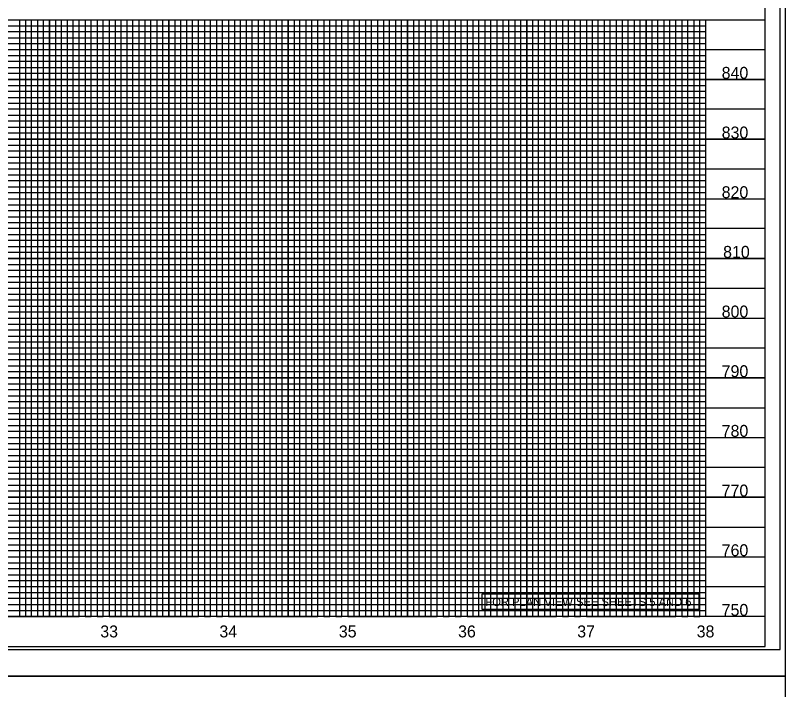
# Model space of a CAD drawing. Extents: x 1755181 to 1757273, y 729911 to 735411.
# Drawn here: x 1756219 to 1756865, y 734300 to 734864 of the extents above; entities that cross this region are included whole.
import ezdxf

# ---------------------------------------------------------------- set-up
doc = ezdxf.new("R2010")
doc.units = 0
for name, color, linetype in [('Exist Vertical Profile Horizontal Axis Label Major', 7, 'Continuous'), ('Exist Vertical Profile Vertical Axis Label', 7, 'Continuous'), ('Prop Grid Mask', 7, 'Continuous'), ('Prop VPI Label', 7, 'Continuous'), ('Scratch_Level_3', 7, 'Continuous'), ('Sheet Cutting Line CELL', 7, 'Continuous'), ('Sheet DOT Grid CELL', 7, 'Continuous'), ('Sheet Plot Border Inside CELL', 7, 'Continuous'), ('Sheet Plot Border Outside CELL', 7, 'Continuous'), ('Sheet Profile CELL', 7, 'Continuous'), ('Sheet Profile Grid Major CELL', 7, 'Continuous'), ('Sheet Profile Grid Middle CELL', 7, 'Continuous'), ('Sheet Profile Grid Minor CELL', 7, 'Continuous')]:
    doc.layers.add(name, color=color, linetype=linetype)

msp = doc.modelspace()

# ---------------------------------------------------------------- linework, layer by layer
at = {"layer": 'Prop Grid Mask'}
msp.add_lwpolyline([(1756610.25, 734379.75), (1756792.01, 734379.75), (1756792.01, 734366.55), (1756610.25, 734366.55)], close=True, dxfattribs=at)
at = {"layer": 'Scratch_Level_3'}
msp.add_lwpolyline([(1755397.67, 734860.78), (1756797.67, 734860.78), (1756797.67, 734360.78), (1755397.67, 734360.78)], close=True, dxfattribs=at)
at = {"layer": 'Sheet Cutting Line CELL'}
msp.add_line((1755180.67, 734310.78), (1756864.67, 734310.78), dxfattribs=at)
at = {"layer": 'Sheet DOT Grid CELL'}
for p, q in [((1755347.67, 734860.78), (1756847.56, 734860.78)), ((1756247.67, 734860.78), (1756247.67, 734360.78)), ((1756297.67, 734860.78), (1756297.67, 734360.78)), ((1756347.67, 734860.78), (1756347.67, 734360.78)), ((1756397.67, 734860.78), (1756397.67, 734360.78)), ((1756447.67, 734860.78), (1756447.67, 734360.78)), ((1756497.67, 734860.78), (1756497.67, 734360.78)), ((1756547.67, 734860.78), (1756547.67, 734360.78)), ((1756597.67, 734860.78), (1756597.67, 734360.78)), ((1756647.67, 734860.78), (1756647.67, 734360.78)), ((1756697.67, 734860.78), (1756697.67, 734360.78)), ((1756747.67, 734860.78), (1756747.67, 734360.78)), ((1756797.67, 734860.78), (1756797.67, 734360.78)), ((1755347.67, 734810.78), (1756847.56, 734810.78)), ((1755347.67, 734760.78), (1756847.56, 734760.78)), ((1755347.67, 734710.78), (1756847.56, 734710.78)), ((1755347.67, 734660.78), (1756847.56, 734660.78)), ((1755347.67, 734610.78), (1756847.56, 734610.78)), ((1755347.67, 734560.78), (1756847.56, 734560.78)), ((1755347.67, 734510.78), (1756847.56, 734510.78)), ((1755347.67, 734460.78), (1756847.56, 734460.78)), ((1755347.67, 734410.78), (1756847.56, 734410.78))]:
    msp.add_line(p, q, dxfattribs=at)
at = {"layer": 'Sheet Plot Border Inside CELL'}
msp.add_lwpolyline([(1755193.67, 734333.23), (1756860.17, 734333.23), (1756860.17, 735388.33), (1755193.67, 735388.33)], close=True, dxfattribs=at)
at = {"layer": 'Sheet Plot Border Outside CELL'}
for points in [[(1755180.67, 734310.78), (1756864.67, 734310.78), (1756864.67, 735410.78), (1755180.67, 735410.78)], [(1755180.67, 733210.78), (1756864.67, 733210.78), (1756864.67, 734310.78), (1755180.67, 734310.78)]]:
    msp.add_lwpolyline(points, close=True, dxfattribs=at)
at = {"layer": 'Sheet Profile CELL'}
for p, q in [((1755347.67, 734860.78), (1756847.67, 734860.78)), ((1756847.67, 734360.78), (1755347.67, 734360.78)), ((1755347.67, 734335.78), (1756847.67, 734335.78))]:
    msp.add_line(p, q, dxfattribs=at)
msp.add_lwpolyline([(1756847.67, 735385.78), (1755347.67, 735385.78), (1755347.67, 734335.78), (1756847.67, 734335.78)], close=True, dxfattribs=at)
at = {"layer": 'Sheet Profile Grid Major CELL'}
for p, q in [((1756247.67, 734860.78), (1756297.67, 734860.78)), ((1756347.67, 734860.78), (1756397.67, 734860.78)), ((1756447.67, 734860.78), (1756497.67, 734860.78)), ((1756547.67, 734860.78), (1756597.67, 734860.78)), ((1756647.67, 734860.78), (1756697.67, 734860.78)), ((1756747.67, 734860.78), (1756797.67, 734860.78)), ((1756747.67, 734360.78), (1756747.67, 734360.78)), ((1756797.67, 734361.07), (1756797.67, 734361.07))]:
    msp.add_line(p, q, dxfattribs=at)
for points in [[(1756197.67, 734360.78), (1756247.67, 734360.78), (1756247.67, 734860.78), (1756297.67, 734860.78), (1756297.67, 734360.78), (1756347.67, 734360.78), (1756347.67, 734860.78), (1756397.67, 734860.78), (1756397.67, 734360.78), (1756447.67, 734360.78), (1756447.67, 734860.78), (1756497.67, 734860.78), (1756497.67, 734360.78), (1756547.67, 734360.78), (1756547.67, 734860.78), (1756597.67, 734860.78), (1756597.67, 734360.78), (1756647.67, 734360.78), (1756647.67, 734860.78), (1756697.67, 734860.78), (1756697.67, 734360.78), (1756747.67, 734360.78), (1756747.67, 734360.78), (1756747.67, 734860.78), (1756797.67, 734860.78), (1756797.67, 734360.78)], [(1756847.67, 734810.78), (1755347.67, 734810.78)], [(1756847.67, 734760.78), (1755347.67, 734760.78), (1755347.67, 734710.78), (1756847.67, 734710.78)], [(1756847.67, 734660.78), (1755347.67, 734660.78), (1755347.67, 734610.78), (1756847.67, 734610.78)], [(1756847.67, 734560.78), (1755347.67, 734560.78), (1755347.67, 734510.78), (1756847.67, 734510.78)], [(1756847.67, 734460.78), (1755347.67, 734460.78), (1755347.67, 734460.78), (1755347.67, 734410.78), (1756847.67, 734410.78)], [(1756847.67, 734360.78), (1755347.67, 734360.78)]]:
    msp.add_lwpolyline(points, dxfattribs=at)
at = {"layer": 'Sheet Profile Grid Middle CELL'}
for points in [[(1756172.67, 734860.78), (1756222.67, 734860.78), (1756222.67, 734360.78), (1756272.67, 734360.78), (1756272.67, 734860.78), (1756322.67, 734860.78), (1756322.67, 734360.78), (1756372.67, 734360.78), (1756372.67, 734860.78), (1756422.67, 734860.78), (1756422.67, 734360.78), (1756472.67, 734360.78), (1756472.67, 734860.78), (1756522.67, 734860.78), (1756522.67, 734360.78), (1756572.67, 734360.78), (1756572.67, 734860.78), (1756622.67, 734860.78), (1756622.67, 734360.78), (1756672.67, 734360.78), (1756672.67, 734860.78), (1756722.67, 734860.78), (1756722.67, 734360.78), (1756772.67, 734360.78), (1756772.67, 734860.78)], [(1755347.67, 734835.78), (1756847.67, 734835.78)], [(1756847.67, 734785.78), (1755347.67, 734785.78), (1755347.67, 734735.78), (1756847.67, 734735.78)], [(1756847.67, 734685.78), (1755347.67, 734685.78), (1755347.67, 734635.78), (1756847.67, 734635.78)], [(1756847.67, 734585.78), (1755347.67, 734585.78), (1755347.67, 734535.78), (1756847.67, 734535.78)], [(1756847.67, 734485.78), (1755347.67, 734485.78), (1755347.67, 734435.78), (1756847.67, 734435.78)], [(1756847.67, 734385.78), (1755347.67, 734385.78)]]:
    msp.add_lwpolyline(points, dxfattribs=at)
at = {"layer": 'Sheet Profile Grid Minor CELL'}
for p, q in [((1755397.67, 734855.78), (1756797.67, 734855.78)), ((1756797.67, 734850.78), (1755397.67, 734850.78)), ((1755397.67, 734845.78), (1756797.67, 734845.78)), ((1756797.67, 734840.78), (1755397.67, 734840.78)), ((1755397.67, 734830.78), (1756797.67, 734830.78)), ((1756797.67, 734825.78), (1755397.67, 734825.78)), ((1755397.67, 734820.78), (1756797.67, 734820.78)), ((1756797.67, 734815.78), (1755397.67, 734815.78)), ((1755397.67, 734805.78), (1756797.67, 734805.78)), ((1756797.67, 734800.78), (1755397.67, 734800.78)), ((1755397.67, 734795.78), (1756797.67, 734795.78)), ((1756797.67, 734790.78), (1755397.67, 734790.78)), ((1755397.67, 734780.78), (1756797.67, 734780.78)), ((1756797.67, 734775.78), (1755397.67, 734775.78)), ((1755397.67, 734770.78), (1756797.67, 734770.78)), ((1756797.67, 734765.78), (1755397.67, 734765.78)), ((1755397.67, 734755.78), (1756797.67, 734755.78)), ((1756797.67, 734750.78), (1755397.67, 734750.78)), ((1755397.67, 734745.78), (1756797.67, 734745.78)), ((1756797.67, 734740.78), (1755397.67, 734740.78)), ((1755397.67, 734730.78), (1756797.67, 734730.78)), ((1756797.67, 734725.78), (1755397.67, 734725.78)), ((1755397.67, 734720.78), (1756797.67, 734720.78)), ((1756797.67, 734715.78), (1755397.67, 734715.78)), ((1755397.67, 734705.78), (1756797.67, 734705.78)), ((1756797.67, 734700.78), (1755397.67, 734700.78)), ((1755397.67, 734695.78), (1756797.67, 734695.78)), ((1756797.67, 734690.78), (1755397.67, 734690.78)), ((1755397.67, 734680.78), (1756797.67, 734680.78)), ((1756797.67, 734675.78), (1755397.67, 734675.78)), ((1755397.67, 734670.78), (1756797.67, 734670.78)), ((1756797.67, 734665.78), (1755397.67, 734665.93)), ((1755397.67, 734655.78), (1756797.67, 734655.78)), ((1756797.67, 734650.78), (1755397.67, 734650.78)), ((1755397.67, 734645.78), (1756797.67, 734645.78)), ((1756797.67, 734640.78), (1755397.67, 734640.78)), ((1755397.67, 734630.78), (1756797.67, 734630.78)), ((1756797.67, 734625.78), (1755397.67, 734625.78)), ((1755397.67, 734620.78), (1756797.67, 734620.78)), ((1756797.67, 734615.78), (1755397.67, 734615.78)), ((1755397.67, 734605.78), (1756797.67, 734605.78)), ((1756797.67, 734600.78), (1755397.67, 734600.78)), ((1755397.67, 734595.78), (1756797.67, 734595.78)), ((1756797.67, 734590.78), (1755397.67, 734590.78)), ((1755397.67, 734580.78), (1756797.67, 734580.78)), ((1756797.67, 734575.78), (1755397.67, 734575.78)), ((1755397.67, 734570.78), (1756797.67, 734570.78)), ((1756797.67, 734565.78), (1755397.67, 734565.78)), ((1755397.67, 734555.78), (1756797.67, 734555.78)), ((1756797.67, 734550.78), (1755397.67, 734550.78)), ((1755397.67, 734545.78), (1756797.67, 734545.78)), ((1756797.67, 734540.78), (1755397.67, 734540.78)), ((1755397.67, 734530.78), (1756797.67, 734530.78)), ((1756797.67, 734525.78), (1755397.67, 734525.78)), ((1755397.67, 734520.78), (1756797.67, 734520.78)), ((1756797.67, 734515.78), (1755397.67, 734515.78)), ((1755397.67, 734505.78), (1756797.67, 734505.78)), ((1756797.67, 734500.78), (1755397.67, 734500.78)), ((1755397.67, 734495.78), (1756797.67, 734495.78)), ((1756797.67, 734490.78), (1755397.67, 734490.78)), ((1755397.67, 734480.78), (1756797.67, 734480.78)), ((1756797.67, 734475.78), (1755397.67, 734475.78)), ((1755397.67, 734470.78), (1756797.67, 734470.78)), ((1756797.67, 734465.78), (1755397.67, 734465.78)), ((1755397.67, 734455.78), (1756797.67, 734455.78)), ((1756797.67, 734450.78), (1755397.67, 734450.78)), ((1755397.67, 734445.78), (1756797.67, 734445.78)), ((1756797.67, 734440.78), (1755397.67, 734440.78)), ((1755397.67, 734430.78), (1756797.67, 734430.78)), ((1756797.67, 734425.78), (1755397.67, 734425.78)), ((1755397.67, 734420.78), (1756797.67, 734420.78)), ((1756797.67, 734415.78), (1755397.67, 734415.78)), ((1755397.67, 734405.78), (1756797.67, 734405.78)), ((1756797.67, 734400.78), (1755397.67, 734400.78)), ((1755397.67, 734395.78), (1756797.67, 734395.78)), ((1756797.67, 734390.78), (1755397.67, 734390.78)), ((1755397.67, 734380.78), (1756797.67, 734380.78)), ((1756797.67, 734375.78), (1755397.67, 734375.78)), ((1755397.67, 734370.78), (1756797.67, 734370.78)), ((1755397.67, 734365.78), (1756797.67, 734365.78)), ((1756797.67, 734365.78), (1756797.67, 734365.78))]:
    msp.add_line(p, q, dxfattribs=at)
for points in [[(1756217.67, 734860.78), (1756227.67, 734860.78), (1756227.67, 734360.78), (1756232.67, 734360.78)], [(1756232.67, 734360.78), (1756232.67, 734860.78), (1756237.67, 734860.78), (1756237.67, 734360.78), (1756242.67, 734360.78), (1756242.67, 734860.78), (1756252.67, 734860.78), (1756252.67, 734360.78), (1756257.67, 734360.78), (1756257.67, 734860.78), (1756262.67, 734860.78), (1756262.67, 734360.78), (1756267.67, 734360.78), (1756267.67, 734860.78), (1756277.67, 734860.78), (1756277.67, 734360.78), (1756282.67, 734360.78), (1756282.67, 734860.78), (1756287.67, 734860.78), (1756287.67, 734360.78), (1756292.67, 734360.78), (1756292.67, 734860.78), (1756302.67, 734860.78), (1756302.67, 734360.78), (1756307.67, 734360.78), (1756307.67, 734860.78), (1756312.67, 734860.78), (1756312.67, 734360.78), (1756317.67, 734360.78), (1756317.67, 734860.78), (1756327.67, 734860.78), (1756327.67, 734360.78), (1756332.67, 734360.78), (1756332.67, 734860.78), (1756337.67, 734860.78), (1756337.67, 734360.78), (1756342.67, 734360.78), (1756342.67, 734860.78), (1756352.67, 734860.78), (1756352.67, 734360.78), (1756357.67, 734360.78), (1756357.67, 734860.78), (1756362.67, 734860.78), (1756362.67, 734360.78), (1756367.67, 734360.78), (1756367.67, 734860.78), (1756377.67, 734860.78), (1756377.67, 734360.78), (1756382.67, 734360.78), (1756382.67, 734860.78), (1756387.67, 734860.78), (1756387.67, 734360.78), (1756392.67, 734360.78), (1756392.67, 734860.78), (1756402.67, 734860.78), (1756402.67, 734360.78), (1756407.67, 734360.78), (1756407.67, 734860.78), (1756412.67, 734860.78), (1756412.67, 734360.78), (1756417.67, 734360.78), (1756417.67, 734860.78), (1756427.67, 734860.78), (1756427.67, 734360.78), (1756432.67, 734360.78), (1756432.67, 734860.78), (1756437.67, 734860.78), (1756437.67, 734360.78), (1756442.67, 734360.78), (1756442.67, 734860.78), (1756452.67, 734860.78), (1756452.67, 734360.78), (1756457.67, 734360.78), (1756457.67, 734860.78), (1756462.67, 734860.78), (1756462.67, 734360.78), (1756467.67, 734360.78), (1756467.67, 734860.78), (1756477.67, 734860.78), (1756477.67, 734360.78), (1756482.67, 734360.78), (1756482.67, 734860.78), (1756487.67, 734860.78), (1756487.67, 734360.78), (1756492.67, 734360.78), (1756492.67, 734860.78), (1756502.67, 734860.78), (1756502.67, 734360.78), (1756507.67, 734360.78), (1756507.67, 734860.78), (1756512.67, 734860.78), (1756512.67, 734360.78), (1756517.67, 734360.78), (1756517.67, 734860.78), (1756527.67, 734860.78), (1756527.67, 734360.78), (1756532.67, 734360.78), (1756532.67, 734860.78), (1756537.67, 734860.78), (1756537.67, 734360.78)], [(1756537.67, 734360.78), (1756542.67, 734360.78), (1756542.67, 734860.78), (1756552.67, 734860.78), (1756552.67, 734360.78), (1756557.67, 734360.78), (1756557.67, 734860.78), (1756562.67, 734860.78), (1756562.67, 734360.78), (1756567.67, 734360.78), (1756567.67, 734860.78), (1756577.67, 734860.78), (1756577.67, 734360.78), (1756582.67, 734360.78), (1756582.67, 734860.78), (1756587.67, 734860.78), (1756587.67, 734360.78), (1756592.67, 734360.78), (1756592.67, 734860.78), (1756602.67, 734860.78), (1756602.67, 734360.78), (1756607.67, 734360.78), (1756607.67, 734860.78), (1756612.67, 734860.78), (1756612.67, 734360.78), (1756617.67, 734360.78), (1756617.67, 734860.78), (1756627.67, 734860.78), (1756627.67, 734360.78), (1756632.67, 734360.78), (1756632.67, 734860.78), (1756637.67, 734860.78), (1756637.67, 734360.78), (1756642.67, 734360.78), (1756642.67, 734860.78), (1756652.67, 734860.78), (1756652.67, 734360.78), (1756657.67, 734360.78), (1756657.67, 734860.78), (1756662.67, 734860.78), (1756662.67, 734360.78), (1756667.67, 734360.78), (1756667.67, 734860.78), (1756677.67, 734860.78), (1756677.67, 734360.78), (1756682.67, 734360.78), (1756682.67, 734860.78), (1756687.67, 734860.78), (1756687.67, 734360.78), (1756692.67, 734360.78), (1756692.67, 734860.78), (1756702.67, 734860.78), (1756702.67, 734360.78), (1756707.67, 734360.78), (1756707.67, 734860.78), (1756712.67, 734860.78), (1756712.67, 734360.78), (1756717.67, 734360.78), (1756717.67, 734860.78), (1756727.67, 734860.78), (1756727.67, 734360.78), (1756732.67, 734360.78), (1756732.67, 734860.78), (1756737.67, 734860.78), (1756737.67, 734360.78), (1756742.67, 734360.78), (1756742.67, 734860.78), (1756752.67, 734860.78), (1756752.67, 734360.78), (1756757.67, 734360.78), (1756757.67, 734860.78), (1756762.67, 734860.78), (1756762.67, 734360.78), (1756767.67, 734360.78), (1756767.67, 734860.78), (1756777.67, 734860.78), (1756777.67, 734360.78), (1756782.67, 734360.78), (1756782.67, 734860.78), (1756787.67, 734860.78), (1756787.67, 734360.78), (1756792.67, 734360.78), (1756792.67, 734860.78), (1756797.67, 734860.78)]]:
    msp.add_lwpolyline(points, dxfattribs=at)

# ---------------------------------------------------------------- texts
at = {"layer": 'Exist Vertical Profile Horizontal Axis Label Major'}
for s, p in [('33', (1756290.28, 734343.28)), ('34', (1756390.12, 734343.28)), ('35', (1756490.21, 734343.28)), ('36', (1756590.15, 734343.28)), ('37', (1756690.01, 734343.28)), ('38', (1756790.14, 734343.28))]:
    msp.add_text(s, height=10, dxfattribs=at).set_placement(p)
at = {"layer": 'Exist Vertical Profile Vertical Axis Label'}
for s, p in [('840', (1756811.1, 734811.32)), ('830', (1756811.1, 734761.32)), ('820', (1756811.1, 734711.32)), ('810', (1756812.3, 734661.32)), ('800', (1756811.1, 734611.32)), ('790', (1756811.1, 734561.32)), ('780', (1756811.1, 734511.32)), ('770', (1756811.1, 734461.32)), ('760', (1756811.1, 734411.32)), ('750', (1756811.1, 734361.32))]:
    msp.add_text(s, height=10, dxfattribs=at).set_placement(p)
at = {"layer": 'Prop VPI Label'}
msp.add_text('FOR PLAN VIEW SEE SHEETS 5 AND 6', height=7, dxfattribs=at).set_placement((1756613.07, 734369.54))

doc.saveas('drawing.dxf')
